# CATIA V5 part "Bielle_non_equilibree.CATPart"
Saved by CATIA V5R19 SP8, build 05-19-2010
Part number: Bielle_non_equilibree
Bounding box of the stored display mesh (mm): x 0 to 55, y -20.981 to 20.981, z -21 to 87.827
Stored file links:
  C:\Users\rcousturie\Desktop\EU_thinkMotion\iao\IAO_MMS_Groupe1\vduret\vduret\vduret\CATIA_disque\Bielle_non_equilibree.CATPart
  C:\Users\rcousturie\Desktop\EU_thinkMotion\iao\IAO_MMS_Groupe1\vduret\vduret\vduret\CATIA_disque\vduret.CATProduct
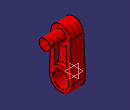
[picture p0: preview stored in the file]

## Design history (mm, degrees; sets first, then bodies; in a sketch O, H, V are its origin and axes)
External parameters (linked from other documents)
  External.diam_int_disque = 30 mm
  External.diam_maneton = 20 mm
  External.excentricite_maneton = 70 mm
  External.extrusion_disque = 25 mm
  External.extrusion_maneton = 30 mm
Body1 (main body)
  Sketch1 on yz-plane, origin (0, 0, 0), H (0, 1, 0), V (0, 0, 1)
    arc A1 centre (0, 70) radius 18 from (17.9835, 70.7714) to (-17.9835, 70.7714) ccw
    point P1 (0, 70)
    arc A2 centre (0, 0) radius 21 from (-20.9807, 0.9) to (20.9807, 0.9) ccw
    circle A3 centre (0, 0) radius 15
    line L1 (17.9835, 70.7714) -> (20.9807, 0.9)
    point P3 (20.9807, 0.9)
    line L2 (-20.9807, 0.9) -> (-17.9835, 70.7714)
    point P4 (-20.9807, 0.9)
    axis line L3 (0, -28.2346) -> (0, 171.7654)
    point P8 (20.9807, 0.9)
    point P9 (-20.9807, 0.9)
    radius A3 = 15 {= External.diam_int_disque /2}
    radius A2 = 21 {= External.diam_int_disque /2+6mm}
    distance P1 H = 70 {= External.excentricite_maneton}
    radius A1 = 18 {= External.diam_maneton /2+8mm}
    tangency: L1 A2, L1 A1, L2 A1, L2 A2
    vertical: L3 V
    coincidence: P1 L3, O L3, L1 P8, L2 P9, P4 A2, P3 A2, P3 P8, P4 P9
  Pad1: profile Sketch1, direction (1, 0, 0), length 25 {= External.extrusion_disque}
  Sketch2 on yz-plane, origin (0, 0, 0), H (0, 1, 0), V (0, 0, 1)
    arc A1 centre (0, 70) radius 16 from (-10.5261, 57.9501) to (10.5261, 57.9501) ccw
    point P1 (0, 70)
    arc A2 centre (0, 0) radius 21 from (12.2812, 17.0344) to (-12.2812, 17.0344) ccw
    line L1 (-10.5261, 57.9501) -> (-12.2812, 17.0344)
    line L2 (10.5261, 57.9501) -> (12.2812, 17.0344)
    reference projected line E1 (-20.9291, 2.1023) -> (-18.797, 51.8059) from edge [end face of Pad1 | face of Pad1 from Sketch1.L2]
    reference projected line E2 (18.797, 51.8059) -> (20.9291, 2.1023) from edge [end face of Pad1 | face of Pad1 from Sketch1.L1]
    reference projected line E3 (-20.9291, 2.1023) -> (-18.797, 51.8059) from edge [end face of Pad1 | face of Pad1 from Sketch1.L2]
    reference projected line E4 (18.797, 51.8059) -> (20.9291, 2.1023) from edge [end face of Pad1 | face of Pad1 from Sketch1.L1]
    radius A1 = 16 {= External.diam_maneton /2+6mm}
    radius A2 = 21 {= External.diam_int_disque /2+6mm}
    distance L1 E3 = 8
    distance L2 E4 = 8
    distance P1 H = 70 {= External.excentricite_maneton}
    coincidence: P1 V
    parallelism: L1 E1, L2 E2
  Sketch3 on end face of Pad1, origin (25, 0, 0), H (0, 1, 0), V (0, 0, 1)
    projected arc E1 centre (0, 70) radius 16 from (-10.5261, 57.9501) to (10.5261, 57.9501) ccw from Sketch2.A1
    projected line E2 (12.2812, 17.0344) -> (10.5261, 57.9501) from Sketch2.L2
    projected line E3 (-10.5261, 57.9501) -> (-12.2812, 17.0344) from Sketch2.L1
    projected arc E4 centre (0, 0) radius 21 from (12.2812, 17.0344) to (-12.2812, 17.0344) ccw from Sketch2.A2
  Pocket1: profile Sketch3, direction (-1, 0, 0), length 8
  Pocket2: profile Sketch2, direction (1, 0, 0), length 8
  Sketch4 on end face of Pad1, origin (25, 0, 0), H (0, 1, 0), V (0, 0, 1)
    circle A1 centre (0, 70) radius 10
    reference projected arc E1 centre (0, 70) radius 18 from (17.9098, 71.8) to (-17.9098, 71.8) ccw from edge [end face of Pad1 | face of Pad1 from Sketch1.A1]
    radius A1 = 10 {= External.diam_maneton /2}
    concentricity: A1 E1
  Pad2: profile Sketch4, direction (1, 0, 0), length 30 {= External.extrusion_maneton}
